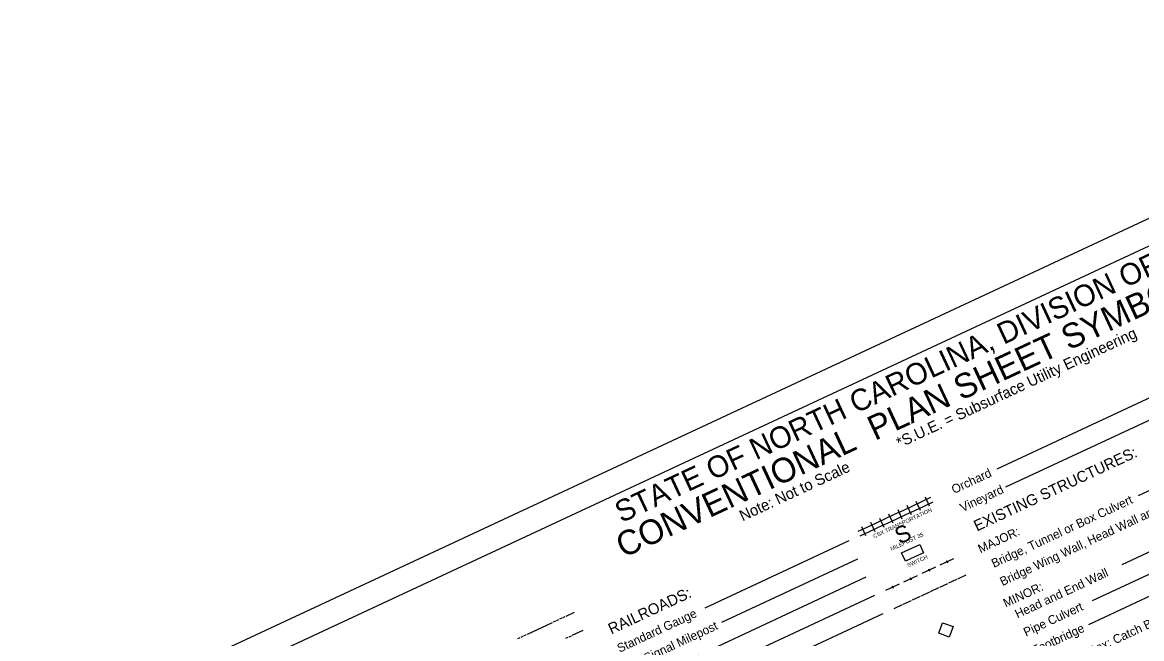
# Model space of a CAD drawing. Extents: x 885291.5 to 885341.7, y 651350.6 to 651393.5.
# Drawn here: x 885291.53 to 885319.4, y 651378.14 to 651393.48 of the extents above; entities that cross this region are included whole.
import ezdxf

# ---------------------------------------------------------------- set-up
doc = ezdxf.new("R2010")
doc.units = 0
doc.layers.add('Sheet Symbology CELL', color=7, linetype='Continuous')
doc.layers.add('Stewart Plot Border Xerox6279 and LJ5000', color=7, linetype='Continuous')

msp = doc.modelspace()

# ---------------------------------------------------------------- linework, layer by layer
at = {"layer": 'Sheet Symbology CELL'}
for p, q in [((885320.436, 651384.529), (885315.793, 651382.363)), ((885320.648, 651384.075), (885316.004, 651381.91)), ((885321.221, 651382.591), (885319.308, 651381.699)), ((885313.699, 651381.447), (885313.926, 651381.553)), ((885313.892, 651381.33), (885313.786, 651381.557)), ((885313.926, 651381.553), (885314.152, 651381.659)), ((885313.978, 651381.44), (885314.205, 651381.545)), ((885314.118, 651381.436), (885314.012, 651381.663)), ((885313.019, 651381.13), (885313.246, 651381.236)), ((885313.212, 651381.013), (885313.106, 651381.24)), ((885313.246, 651381.236), (885313.472, 651381.342)), ((885313.299, 651381.123), (885313.525, 651381.228)), ((885313.438, 651381.119), (885313.333, 651381.346)), ((885313.472, 651381.342), (885313.699, 651381.447)), ((885313.525, 651381.228), (885313.752, 651381.334)), ((885313.665, 651381.225), (885313.559, 651381.451)), ((885313.752, 651381.334), (885313.978, 651381.44)), ((885321.808, 651381.332), (885318.901, 651379.976)), ((885312.34, 651380.814), (885312.566, 651380.919)), ((885312.532, 651380.696), (885312.426, 651380.923)), ((885312.566, 651380.919), (885312.793, 651381.025)), ((885312.619, 651380.806), (885312.846, 651380.912)), ((885312.759, 651380.802), (885312.653, 651381.029)), ((885312.793, 651381.025), (885313.019, 651381.13)), ((885312.846, 651380.912), (885313.072, 651381.017)), ((885312.985, 651380.908), (885312.88, 651381.134)), ((885313.072, 651381.017), (885313.299, 651381.123)), ((885312.392, 651380.7), (885312.619, 651380.806)), ((885322.019, 651380.879), (885318.163, 651379.081)), ((885312.109, 651380.575), (885308.52, 651378.901)), ((885322.231, 651380.426), (885318.073, 651378.487)), ((885312.32, 651380.122), (885308.932, 651378.541)), ((885314.383, 651379.98), (885314.723, 651380.139)), ((885314.54, 651380.088), (885314.566, 651380.031)), ((885313.93, 651379.769), (885314.27, 651379.927)), ((885314.087, 651379.876), (885314.113, 651379.82)), ((885312.532, 651379.668), (885307.662, 651377.398)), ((885313.024, 651379.346), (885313.364, 651379.505)), ((885313.477, 651379.557), (885313.817, 651379.716)), ((885313.634, 651379.665), (885313.66, 651379.608)), ((885314.368, 651379.421), (885314.572, 651379.516)), ((885314.595, 651379.527), (885314.799, 651379.622)), ((885314.821, 651379.633), (885315.025, 651379.728)), ((885313.181, 651379.454), (885313.207, 651379.397)), ((885313.915, 651379.21), (885314.119, 651379.305)), ((885314.141, 651379.316), (885314.345, 651379.411)), ((885312.743, 651379.215), (885308.978, 651377.46)), ((885313.235, 651378.893), (885313.439, 651378.988)), ((885313.462, 651378.999), (885313.666, 651379.094)), ((885313.688, 651379.104), (885313.892, 651379.199)), ((885304.988, 651378.667), (885305.044, 651378.693)), ((885305.067, 651378.704), (885305.278, 651378.802)), ((885312.954, 651378.762), (885309.189, 651377.006)), ((885312.954, 651378.762), (885309.189, 651377.006)), ((885304.104, 651378.255), (885304.727, 651378.545)), ((885304.75, 651378.556), (885304.806, 651378.582)), ((885304.829, 651378.593), (885304.886, 651378.619)), ((885304.908, 651378.63), (885304.965, 651378.656)), ((885303.866, 651378.144), (885303.923, 651378.17)), ((885303.945, 651378.181), (885304.002, 651378.207)), ((885304.025, 651378.218), (885304.081, 651378.244)), ((885305.06, 651378.149), (885305.117, 651378.176)), ((885305.14, 651378.186), (885305.196, 651378.213)), ((885305.219, 651378.223), (885305.489, 651378.349))]:
    msp.add_line(p, q, dxfattribs=at)
for points in [[(885329.923, 651392.736), (885295.937, 651376.888), (885307.02, 651353.12), (885341.006, 651368.969)], [(885313.419, 651380.274), (885313.872, 651380.485), (885313.968, 651380.279), (885313.515, 651380.068)], [(885314.346, 651378.276), (885314.44, 651378.535), (885314.7, 651378.441), (885314.606, 651378.181)]]:
    msp.add_lwpolyline(points, close=True, dxfattribs=at)
at = {"layer": 'Stewart Plot Border Xerox6279 and LJ5000'}
msp.add_lwpolyline([(885303.148, 651350.597), (885341.666, 651368.559), (885330.044, 651393.482), (885291.526, 651375.521)], close=True, dxfattribs=at)

# ---------------------------------------------------------------- texts
at = {"layer": 'Sheet Symbology CELL'}
for s, height, p in [('STATE OF NORTH CAROLINA, DIVISION OF HIGHWAYS', 0.53547, (885306.441, 651381.015)), ('CONVENTIONAL  PLAN SHEET SYMBOLS', 0.61201, (885306.492, 651380.14)), ('*S.U.E. = Subsurface Utility Engineering', 0.275, (885313.369, 651382.879)), ('EXISTING STRUCTURES:', 0.275, (885315.296, 651380.806)), ('Note: Not to Scale', 0.275, (885309.461, 651381.057)), ('Orchard', 0.2188, (885314.725, 651381.741)), ('Vineyard', 0.2188, (885314.937, 651381.288)), ('Bridge Wing Wall, Head Wall and End Wall', 0.21875, (885315.93, 651379.447)), ('Bridge, Tunnel or Box Culvert', 0.21875, (885315.719, 651379.9)), ('CSX TRANSPORTATION', 0.1, (885312.741, 651380.636)), ('S', 0.412, (885313.37, 651380.483)), ('MILEPOST 35', 0.1, (885313.168, 651380.323)), ('MAJOR:', 0.2188, (885315.383, 651380.264)), ('SWITCH', 0.1, (885313.587, 651379.911)), ('Head and End Wall', 0.21875, (885316.306, 651378.641)), ('RAILROADS:', 0.275, (885306.193, 651378.242)), ('MINOR:', 0.2188, (885316.013, 651378.911)), ('Drainage Box: Catch Basin, DI or JB', 0.21875, (885316.987, 651377.181)), ('Pipe Culvert', 0.21875, (885316.517, 651378.188)), ('Standard Gauge', 0.21875, (885306.398, 651377.787)), ('RR Signal Milepost', 0.21875, (885306.609, 651377.334)), ('Footbridge', 0.2188, (885316.729, 651377.735))]:
    msp.add_text(s, height=height, rotation=25, dxfattribs=at).set_placement(p)

doc.saveas('drawing.dxf')
